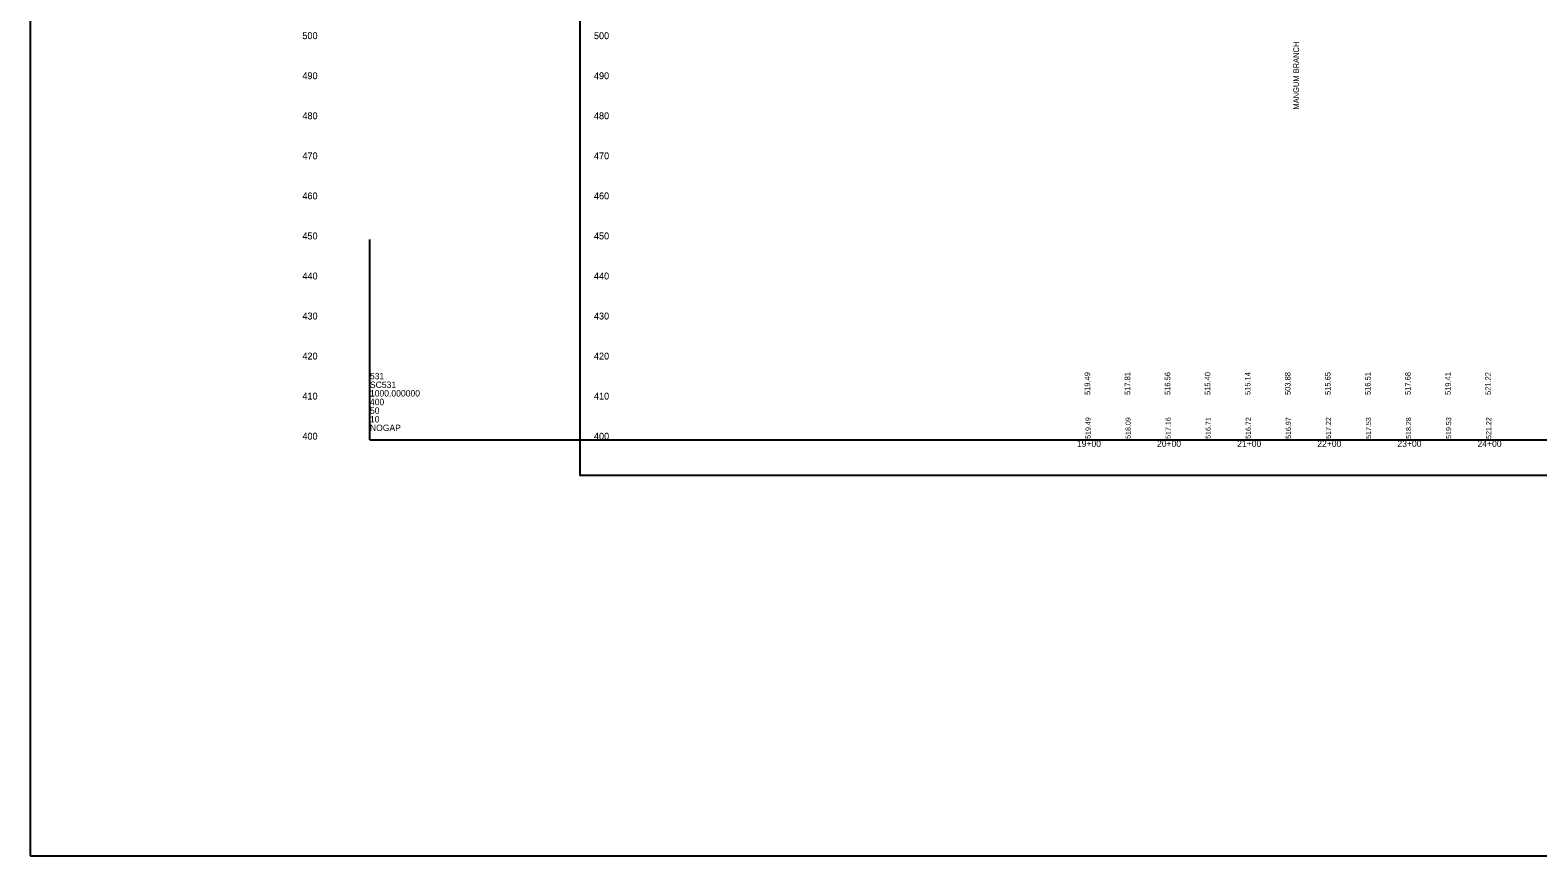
# Model space of a CAD drawing. Extents: x 2167726 to 2171326, y 1079832 to 1082032.
# Drawn here: x 2167726 to 2169608, y 1079832 to 1080863 of the extents above; entities that cross this region are included whole.
import ezdxf

# ---------------------------------------------------------------- set-up
doc = ezdxf.new("R2010")
doc.units = 0
for name, color, linetype in [('RD_DDB_ElevTX', 7, 'Continuous'), ('RD_DDB_Profile_Lbl', 7, 'Continuous'), ('RD_DDB_StaTX', 7, 'Continuous'), ('RD_DDB_StripGrade', 7, 'Continuous'), ('RD_GPK_Profile_Cell', 7, 'Continuous'), ('RD_SHT_IplotShp', 7, 'Continuous'), ('RD_SHT_ShtClip', 7, 'Continuous')]:
    doc.layers.add(name, color=color, linetype=linetype)

msp = doc.modelspace()

# ---------------------------------------------------------------- linework, layer by layer
at = {"layer": 'RD_GPK_Profile_Cell'}
for q in [(2168150.2, 1080601.5), (2170902, 1080351.5), (2168150.2, 1080351.5)]:
    msp.add_line((2168150.2, 1080351.5), q, dxfattribs=at)
at = {"layer": 'RD_SHT_IplotShp'}
msp.add_lwpolyline([(2167726.1, 1079832), (2171326.1, 1079832), (2171326.1, 1082032), (2167726.1, 1082032)], close=True, dxfattribs=at)
at = {"layer": 'RD_SHT_ShtClip'}
msp.add_lwpolyline([(2168412.7, 1081406.6), (2170212.7, 1081406.6), (2170212.7, 1080306.6), (2168412.7, 1080306.6)], close=True, dxfattribs=at)

# ---------------------------------------------------------------- texts
at = {"layer": 'RD_DDB_ElevTX'}
for s, p in [('500', (2168065.9, 1080851.7)), ('500', (2168065.9, 1080851.5)), ('500', (2168429.8, 1080851.7)), ('500', (2168429.8, 1080851.5)), ('490', (2168065.9, 1080801.7)), ('490', (2168065.9, 1080801.5)), ('490', (2168429.8, 1080801.7)), ('490', (2168429.8, 1080801.5)), ('480', (2168065.9, 1080751.7)), ('480', (2168065.9, 1080751.5)), ('480', (2168429.8, 1080751.7)), ('480', (2168429.8, 1080751.5)), ('470', (2168065.9, 1080701.7)), ('470', (2168065.9, 1080701.5)), ('470', (2168429.8, 1080701.7)), ('470', (2168429.8, 1080701.5)), ('460', (2168065.9, 1080651.7)), ('460', (2168065.9, 1080651.5)), ('460', (2168429.8, 1080651.7)), ('460', (2168429.8, 1080651.5)), ('450', (2168065.9, 1080601.7)), ('450', (2168065.9, 1080601.5)), ('450', (2168429.8, 1080601.7)), ('450', (2168429.8, 1080601.5)), ('440', (2168065.9, 1080551.7)), ('440', (2168065.9, 1080551.5)), ('440', (2168429.8, 1080551.7)), ('440', (2168429.8, 1080551.5)), ('430', (2168065.9, 1080501.7)), ('430', (2168065.9, 1080501.5)), ('430', (2168429.8, 1080501.7)), ('430', (2168429.8, 1080501.5)), ('420', (2168065.9, 1080451.7)), ('420', (2168065.9, 1080451.5)), ('420', (2168429.8, 1080451.7)), ('420', (2168429.8, 1080451.5)), ('410', (2168065.9, 1080401.7)), ('410', (2168065.9, 1080401.5)), ('410', (2168429.8, 1080401.7)), ('410', (2168429.8, 1080401.5)), ('400', (2168065.9, 1080351.7)), ('400', (2168065.9, 1080351.5)), ('400', (2168429.8, 1080351.7)), ('400', (2168429.8, 1080351.5))]:
    msp.add_text(s, height=8.5, dxfattribs=at).set_placement(p)
at = {"layer": 'RD_DDB_Profile_Lbl'}
msp.add_text('MANGUM BRANCH', height=7, rotation=90, dxfattribs=at).set_placement((2169309.7, 1080763.6))
at = {"layer": 'RD_DDB_StaTX'}
for s, p in [('19+00', (2169032.6, 1080342.5)), ('20+00', (2169132.6, 1080342.5)), ('21+00', (2169232.6, 1080342.5)), ('22+00', (2169332.6, 1080342.5)), ('23+00', (2169432.6, 1080342.5)), ('24+00', (2169532.6, 1080342.5))]:
    msp.add_text(s, height=8, dxfattribs=at).set_placement(p)
at = {"layer": 'RD_DDB_StripGrade'}
for s, height, p in [('519.49', 7, (2169049.2, 1080407.3)), ('517.81', 7, (2169099.2, 1080407.3)), ('516.56', 7, (2169149.2, 1080407.3)), ('515.40', 7, (2169199.2, 1080407.3)), ('515.14', 7, (2169249.2, 1080407.3)), ('503.88', 7, (2169299.2, 1080407.3)), ('515.65', 7, (2169349.2, 1080407.3)), ('516.51', 7, (2169399.2, 1080407.3)), ('517.68', 7, (2169449.2, 1080407.3)), ('519.41', 7, (2169499.2, 1080407.3)), ('521.22', 7, (2169549.2, 1080407.3)), ('519.49', 6.4, (2169049.7, 1080352.5)), ('518.09', 6.4, (2169099.7, 1080352.5)), ('517.16', 6.4, (2169149.7, 1080352.5)), ('516.71', 6.4, (2169199.7, 1080352.5)), ('516.72', 6.4, (2169249.7, 1080352.5)), ('516.97', 6.4, (2169299.7, 1080352.5)), ('517.22', 6.4, (2169349.7, 1080352.5)), ('517.53', 6.4, (2169399.7, 1080352.5)), ('518.28', 6.4, (2169449.7, 1080352.5)), ('519.53', 6.4, (2169499.7, 1080352.5)), ('521.22', 6.4, (2169549.7, 1080352.5))]:
    msp.add_text(s, height=height, rotation=90, dxfattribs=at).set_placement(p)
at = {"layer": 'RD_GPK_Profile_Cell'}
for s, p in [('531', (2168150.2, 1080426.9)), ('SC531', (2168150.2, 1080416.1)), ('400', (2168150.2, 1080394.6)), ('1000.000000', (2168150.2, 1080405.4)), ('50', (2168150.2, 1080383.8)), ('10', (2168150.2, 1080373)), ('NOGAP', (2168150.2, 1080362.3))]:
    msp.add_text(s, height=8, dxfattribs=at).set_placement(p)

doc.saveas('drawing.dxf')
